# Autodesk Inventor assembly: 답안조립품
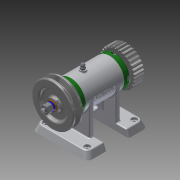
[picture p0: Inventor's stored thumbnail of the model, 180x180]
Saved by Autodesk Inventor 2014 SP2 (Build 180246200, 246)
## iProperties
Created: 2016-07
Part Number: 답안조립품
Document SubType Name: Assembly
Designer: 거성
Author: 거성
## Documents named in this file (16)
- C:\Users\거성\Desktop\460708V1018\답안조립품.iam
- C:\Users\거성\Desktop\460708V1018\본체.ipt
- C:\Users\거성\Desktop\460708V1018\커버.ipt
- C:\Users\거성\Desktop\460708V1018\베어링 15 x 32 x 9.ipt
- C:\Users\거성\Desktop\460708V1018\오일 실 15 25 7.ipt
- C:\Users\거성\Desktop\460708V1018\축.ipt
- C:\Users\거성\Desktop\460708V1018\V벨트풀리.ipt
- C:\Users\거성\Desktop\460708V1018\키 3 x 3 x 12.ipt
- C:\Users\거성\Desktop\460708V1018\스퍼기어.ipt
- C:\Users\거성\Desktop\460708V1018\와셔 8x17.ipt
- C:\Users\거성\Desktop\460708V1018\스프링와셔 8.ipt
- C:\Users\거성\Desktop\460708V1018\너트 M 8.ipt
- C:\Users\거성\Desktop\460708V1018\니플 M 6 x 0.75.ipt
- C:\Users\거성\Desktop\460708V1018\와셔 6x11.5.ipt
- C:\Users\거성\Desktop\460708V1018\볼트 M 6 x 8.ipt
- C:\Users\거성\Desktop\460708V1018\볼트 M4 x 12.ipt
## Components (11 placed, 3 different names)
1. KS B 2023 6002 - 15 x 32 x 9:1
2. KS B 2023 6002 - 15 x 32 x 9:2
3. V벨트풀리:1 — 각도:2
4. ISO 4762 M4 x 12:2
5. ISO 4762 M4 x 12:3
6. ISO 4762 M4 x 12:4
7. ISO 4762 M4 x 12:5
8. ISO 4762 M4 x 12:1
9. ISO 4762 M4 x 12:6
10. ISO 4762 M4 x 12:7
11. ISO 4762 M4 x 12:8
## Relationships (1: Angle 1)
- 각도:2 [Angle]: V벨트풀리:1
